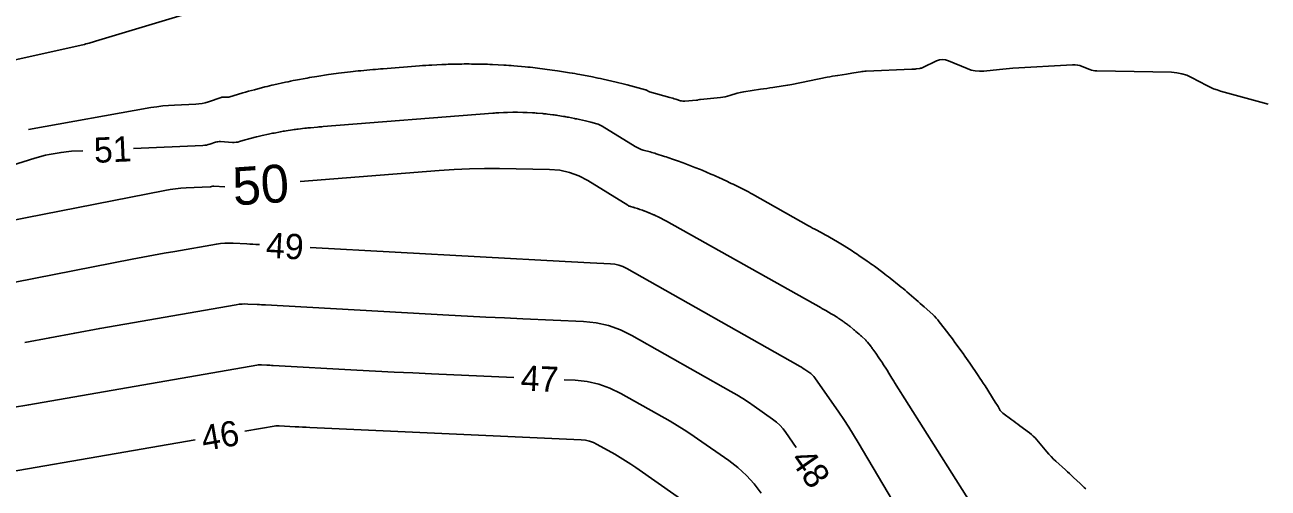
# Model space of a CAD drawing. Extents: x 2384780 to 2405861, y 547869 to 573706.
# Drawn here: x 2389798.2 to 2389896.5, y 552294.5 to 552331.2 of the extents above; entities that cross this region are included whole.
import ezdxf

# ---------------------------------------------------------------- set-up
doc = ezdxf.new("R2010")
doc.units = 0
doc.layers.add('Old_Level_60', color=7, linetype='Continuous')
doc.layers.add('Old_Level_61', color=7, linetype='Continuous')

msp = doc.modelspace()

# ---------------------------------------------------------------- linework, layer by layer
at = {"layer": 'Old_Level_60'}
for points in [[(2389788.7195, 552326.3875), (2389790.72825, 552326.88275), (2389792.092, 552327.21475), (2389793.45775, 552327.5385), (2389794.82525, 552327.854), (2389796.19475, 552328.1615), (2389802.73375, 552329.609), (2389802.86175, 552329.6385), (2389802.98925, 552329.6705), (2389803.116, 552329.705), (2389803.242, 552329.742), (2389803.653, 552329.8665), (2389803.741, 552329.893), (2389803.829, 552329.91975), (2389803.91725, 552329.94625), (2389804.00525, 552329.97275), (2389822.38525, 552335.50225)], [(2389798.453, 552322.90375), (2389808.1335, 552324.6305), (2389808.59675, 552324.70525), (2389809.06175, 552324.7645), (2389809.52825, 552324.8085), (2389809.99675, 552324.83725), (2389811.675, 552324.912), (2389811.929, 552324.932), (2389812.18, 552324.96975), (2389812.42775, 552325.02475), (2389812.67225, 552325.097), (2389813.688, 552325.4365), (2389813.74725, 552325.45325), (2389813.807, 552325.464), (2389813.8675, 552325.46875), (2389813.929, 552325.46775), (2389814.1305, 552325.455), (2389814.1735, 552325.454), (2389814.21625, 552325.457), (2389814.25825, 552325.4635), (2389814.3, 552325.474), (2389815.38925, 552325.79475), (2389815.623, 552325.8625), (2389815.85725, 552325.9285), (2389816.092, 552325.99225), (2389816.32725, 552326.05425), (2389817.1545, 552326.26825), (2389817.332, 552326.31325), (2389817.51, 552326.357), (2389817.688, 552326.399), (2389817.86675, 552326.4395), (2389818.7855, 552326.64375), (2389818.9825, 552326.68675), (2389819.18, 552326.72825), (2389819.37775, 552326.76775), (2389819.57575, 552326.806), (2389820.48225, 552326.9765), (2389820.6765, 552327.01225), (2389820.871, 552327.04625), (2389821.066, 552327.07875), (2389821.26125, 552327.1095), (2389822.18825, 552327.25175), (2389822.387, 552327.28125), (2389822.586, 552327.30925), (2389822.78525, 552327.33575), (2389822.9845, 552327.3605), (2389823.925, 552327.4735), (2389824.12675, 552327.497), (2389824.3285, 552327.51875), (2389824.5305, 552327.539), (2389824.7325, 552327.5575), (2389825.69175, 552327.64125), (2389825.8975, 552327.659), (2389826.103, 552327.6765), (2389826.30875, 552327.69325), (2389826.51425, 552327.70975), (2389829.38675, 552327.93725), (2389829.629, 552327.95575), (2389829.8715, 552327.97275), (2389830.114, 552327.988), (2389830.3565, 552328.00175), (2389831.149, 552328.04425), (2389831.31875, 552328.0525), (2389831.48875, 552328.0595), (2389831.65875, 552328.06475), (2389831.82875, 552328.06875), (2389832.73325, 552328.08525), (2389832.927, 552328.088), (2389833.121, 552328.089), (2389833.31475, 552328.08825), (2389833.5085, 552328.086), (2389834.39275, 552328.07125), (2389834.58225, 552328.06725), (2389834.77175, 552328.06175), (2389834.961, 552328.05425), (2389835.15025, 552328.04525), (2389836.058, 552327.998), (2389836.2525, 552327.987), (2389836.44675, 552327.97425), (2389836.641, 552327.96), (2389836.835, 552327.94375), (2389837.7565, 552327.863), (2389837.954, 552327.845), (2389838.15125, 552327.825), (2389838.34825, 552327.80325), (2389838.545, 552327.78), (2389839.4875, 552327.66375), (2389839.68925, 552327.638), (2389839.891, 552327.6105), (2389840.09225, 552327.58125), (2389840.2935, 552327.55025), (2389841.25875, 552327.39675), (2389841.4655, 552327.363), (2389841.67175, 552327.3275), (2389841.87775, 552327.29025), (2389842.0835, 552327.25125), (2389843.07675, 552327.0585), (2389843.28925, 552327.01625), (2389843.5015, 552326.972), (2389843.71325, 552326.92625), (2389843.92475, 552326.8785)], [(2389843.92475, 552326.8785), (2389844.94875, 552326.6425), (2389845.16775, 552326.591), (2389845.3865, 552326.53775), (2389845.60475, 552326.48275), (2389845.8225, 552326.42575), (2389847.2715, 552326.041), (2389847.304, 552326.031), (2389847.3355, 552326.01875), (2389847.366, 552326.00425), (2389847.39575, 552325.9875), (2389847.4905, 552325.92875), (2389847.51125, 552325.917), (2389847.5325, 552325.90675), (2389847.5545, 552325.898), (2389847.57725, 552325.89075), (2389849.18925, 552325.44225), (2389849.30775, 552325.4085), (2389849.426, 552325.374), (2389849.544, 552325.3385), (2389849.6615, 552325.302), (2389850.0455, 552325.18125), (2389850.128, 552325.1595), (2389850.21175, 552325.14575), (2389850.29625, 552325.14025), (2389850.38175, 552325.143), (2389851.3085, 552325.2155), (2389851.3405, 552325.21875), (2389851.37225, 552325.22375), (2389851.4035, 552325.23025), (2389851.43475, 552325.23825), (2389851.536, 552325.26675), (2389851.55775, 552325.2725), (2389851.57975, 552325.27725), (2389851.60175, 552325.281), (2389851.62425, 552325.28375), (2389853.20075, 552325.44425), (2389853.388, 552325.468), (2389853.57325, 552325.50025), (2389853.757, 552325.54125), (2389853.93875, 552325.59125), (2389854.53, 552325.7685), (2389854.65725, 552325.80425), (2389854.7855, 552325.8355), (2389854.91475, 552325.862), (2389855.045, 552325.88425), (2389856.369, 552326.0855), (2389856.616, 552326.12275), (2389856.863, 552326.16025), (2389857.11, 552326.19725), (2389857.35725, 552326.23425), (2389858.16425, 552326.355), (2389858.337, 552326.38175), (2389858.5095, 552326.41075), (2389858.6815, 552326.442), (2389858.85325, 552326.475), (2389861.65625, 552327.034), (2389861.86325, 552327.0745), (2389862.0705, 552327.113), (2389862.27825, 552327.1495), (2389862.48625, 552327.18425), (2389863.16625, 552327.295), (2389863.312, 552327.3185), (2389863.45775, 552327.342), (2389863.60375, 552327.36525), (2389863.7495, 552327.3885), (2389864.27675, 552327.472), (2389864.39, 552327.48825), (2389864.5035, 552327.50125), (2389864.61725, 552327.511), (2389864.73125, 552327.5175), (2389868.3535, 552327.67025), (2389868.44, 552327.67475), (2389868.52625, 552327.68125), (2389868.6125, 552327.6895), (2389868.6985, 552327.6995), (2389868.9795, 552327.73575), (2389869.039, 552327.74575), (2389869.097, 552327.7605), (2389869.15375, 552327.78), (2389869.209, 552327.80375), (2389870.29525, 552328.32675), (2389870.52875, 552328.412), (2389870.76325, 552328.44425), (2389870.99925, 552328.42325), (2389871.23625, 552328.349), (2389872.71625, 552327.72125), (2389873.03675, 552327.60825), (2389873.36325, 552327.53825), (2389873.69625, 552327.51125), (2389874.0355, 552327.5275), (2389875.2695, 552327.66325), (2389875.534, 552327.69075), (2389875.79875, 552327.7145), (2389876.064, 552327.73475), (2389876.32925, 552327.75175), (2389881.06425, 552328.02025), (2389881.26175, 552328.02075), (2389881.4555, 552328), (2389881.64575, 552327.95775), (2389881.8325, 552327.894)], [(2389881.8325, 552327.894), (2389882.437, 552327.651), (2389882.56775, 552327.60525), (2389882.701, 552327.5715), (2389882.83675, 552327.5505), (2389882.975, 552327.5415), (2389888.8875, 552327.428), (2389889.30275, 552327.39625), (2389889.70575, 552327.3175), (2389890.09675, 552327.1915), (2389890.4755, 552327.0185), (2389891.693, 552326.37625), (2389891.957, 552326.246), (2389892.2265, 552326.13025), (2389892.502, 552326.0295), (2389892.78325, 552325.94325), (2389896.54125, 552324.89975)], [(2389806.74775, 552321.395), (2389812.2445, 552321.64), (2389812.386, 552321.651), (2389812.52575, 552321.672), (2389812.66375, 552321.70275), (2389812.8, 552321.743), (2389813.24175, 552321.89075), (2389813.337, 552321.9175), (2389813.4335, 552321.935), (2389813.5315, 552321.94275), (2389813.6305, 552321.94125), (2389814.582, 552321.88025), (2389814.72475, 552321.8775), (2389814.86625, 552321.887), (2389815.00625, 552321.90875), (2389815.14475, 552321.94325), (2389815.59525, 552322.076), (2389815.692, 552322.104), (2389815.78875, 552322.13125), (2389815.886, 552322.15775), (2389815.98325, 552322.18325), (2389816.49575, 552322.316), (2389816.60575, 552322.34375), (2389816.716, 552322.37075), (2389816.8265, 552322.39675), (2389816.937, 552322.422), (2389817.43775, 552322.53325), (2389817.545, 552322.55675), (2389817.65275, 552322.57925), (2389817.7605, 552322.601), (2389817.86825, 552322.62175), (2389818.38125, 552322.71825), (2389818.491, 552322.73825), (2389818.60125, 552322.75775), (2389818.7115, 552322.776), (2389818.822, 552322.7935), (2389819.3405, 552322.873), (2389819.45175, 552322.8895), (2389819.563, 552322.90525), (2389819.6745, 552322.92), (2389819.786, 552322.93375), (2389820.314, 552322.99725), (2389820.42725, 552323.0105), (2389820.5405, 552323.02275), (2389820.65375, 552323.034), (2389820.76725, 552323.0445), (2389821.30525, 552323.0915), (2389821.4205, 552323.1015), (2389821.53575, 552323.111), (2389821.651, 552323.1205), (2389821.76625, 552323.12975), (2389835.19225, 552324.19325), (2389835.30625, 552324.20175), (2389835.42025, 552324.20975), (2389835.5345, 552324.217), (2389835.6485, 552324.2235), (2389836.02175, 552324.2435), (2389836.10175, 552324.2475), (2389836.18175, 552324.25075), (2389836.26175, 552324.25325), (2389836.34175, 552324.255), (2389836.7675, 552324.26275), (2389836.85875, 552324.264), (2389836.95, 552324.2645), (2389837.04125, 552324.26425), (2389837.1325, 552324.263), (2389837.54875, 552324.25625), (2389837.638, 552324.25425), (2389837.72725, 552324.25175), (2389837.81625, 552324.24825), (2389837.9055, 552324.244), (2389838.33275, 552324.22175), (2389838.42425, 552324.2165), (2389838.51575, 552324.2105), (2389838.607, 552324.20375), (2389838.6985, 552324.19625), (2389839.13225, 552324.15825), (2389839.22525, 552324.14975), (2389839.318, 552324.14025), (2389839.41075, 552324.13), (2389839.5035, 552324.119), (2389839.94725, 552324.0645), (2389840.04225, 552324.05225), (2389840.137, 552324.03925), (2389840.23175, 552324.0255), (2389840.3265, 552324.011), (2389840.781, 552323.93875), (2389840.87825, 552323.92275), (2389840.9755, 552323.90625), (2389841.0725, 552323.8885), (2389841.16925, 552323.87025), (2389841.63675, 552323.7795), (2389841.737, 552323.7595), (2389841.83675, 552323.73875), (2389841.9365, 552323.71725), (2389842.036, 552323.69475), (2389842.518, 552323.5835), (2389842.62125, 552323.5595), (2389842.72425, 552323.53425), (2389842.827, 552323.5085), (2389842.9295, 552323.4815)], [(2389842.9295, 552323.4815), (2389843.42875, 552323.349), (2389843.534, 552323.31675), (2389843.63625, 552323.27725), (2389843.73525, 552323.23025), (2389843.831, 552323.17575), (2389846.4485, 552321.5575), (2389846.6015, 552321.47025), (2389846.75925, 552321.39425), (2389846.922, 552321.32975), (2389847.08975, 552321.27675), (2389847.646, 552321.122), (2389847.765, 552321.08825), (2389847.88375, 552321.0535), (2389848.00225, 552321.018), (2389848.1205, 552320.98125), (2389848.76925, 552320.777), (2389848.908, 552320.7325), (2389849.0465, 552320.687), (2389849.1845, 552320.6405), (2389849.322, 552320.59275), (2389849.96525, 552320.3665), (2389850.103, 552320.31725), (2389850.24025, 552320.26725), (2389850.377, 552320.216), (2389850.5135, 552320.1635), (2389851.183, 552319.903), (2389851.32625, 552319.84675), (2389851.469, 552319.78925), (2389851.6115, 552319.73075), (2389851.75325, 552319.671), (2389852.443, 552319.37725), (2389852.5905, 552319.31375), (2389852.7375, 552319.249), (2389852.884, 552319.18325), (2389853.03, 552319.11625), (2389853.745, 552318.785), (2389853.898, 552318.7135), (2389854.05025, 552318.6405), (2389854.202, 552318.56675), (2389854.35325, 552318.4915), (2389855.09525, 552318.11925), (2389855.25375, 552318.0385), (2389855.41125, 552317.95575), (2389855.56775, 552317.8715), (2389855.72325, 552317.785), (2389860.16525, 552315.28525), (2389860.329, 552315.19375), (2389860.493, 552315.1035), (2389860.65775, 552315.01375), (2389860.823, 552314.92525), (2389861.3635, 552314.6375), (2389861.479, 552314.57525), (2389861.594, 552314.512), (2389861.70825, 552314.44775), (2389861.822, 552314.38225), (2389862.4565, 552314.01275), (2389862.592, 552313.93275), (2389862.72675, 552313.85175), (2389862.861, 552313.7695), (2389862.99425, 552313.686), (2389863.6255, 552313.286), (2389863.76025, 552313.19975), (2389863.89425, 552313.112), (2389864.0275, 552313.02325), (2389864.16, 552312.93325), (2389864.82, 552312.47975), (2389864.961, 552312.382), (2389865.10125, 552312.28275), (2389865.24025, 552312.18225), (2389865.3785, 552312.0805), (2389866.0615, 552311.573), (2389866.2075, 552311.46375), (2389866.35225, 552311.353), (2389866.49625, 552311.241), (2389866.639, 552311.12775), (2389867.35175, 552310.558), (2389867.50375, 552310.43525), (2389867.655, 552310.31125), (2389867.805, 552310.186), (2389867.95375, 552310.05925), (2389868.69925, 552309.4195), (2389868.8585, 552309.282), (2389869.0165, 552309.143), (2389869.1735, 552309.0025), (2389869.32925, 552308.861), (2389869.997, 552308.24925), (2389870.13725, 552308.11525), (2389870.271, 552307.97575), (2389870.399, 552307.8305), (2389870.5205, 552307.67975), (2389871.194, 552306.8075), (2389871.3375, 552306.62), (2389871.4795, 552306.43125), (2389871.62025, 552306.24175), (2389871.75925, 552306.051), (2389872.40075, 552305.16375), (2389872.5375, 552304.973), (2389872.67275, 552304.7815), (2389872.80675, 552304.58875), (2389872.93925, 552304.39525)], [(2389787.4015, 552317.024), (2389798.94025, 552320.63875), (2389799.2215, 552320.722), (2389799.50475, 552320.796), (2389799.79025, 552320.86125), (2389800.078, 552320.91725), (2389801.02175, 552321.0855), (2389801.22425, 552321.11825), (2389801.42775, 552321.14425), (2389801.63175, 552321.1635), (2389801.8365, 552321.176), (2389802.75175, 552321.21675)], [(2389786.4935, 552308.68425), (2389806.6455, 552312.63175), (2389807.48875, 552312.79475), (2389808.33275, 552312.953), (2389809.17775, 552313.1065), (2389810.0235, 552313.25575), (2389813.3155, 552313.827), (2389813.6445, 552313.87475), (2389813.97475, 552313.9035), (2389814.306, 552313.91325), (2389814.63825, 552313.90425), (2389815.72575, 552313.84425), (2389815.95875, 552313.8315), (2389816.19175, 552313.8185), (2389816.42475, 552313.80575), (2389816.65775, 552313.79275), (2389816.72725, 552313.789)], [(2389820.72125, 552313.5685), (2389840.9175, 552312.4535), (2389841.41, 552312.427), (2389841.9025, 552312.4015), (2389842.39525, 552312.3775), (2389842.888, 552312.35475), (2389844.49775, 552312.282), (2389844.837, 552312.24725), (2389845.16525, 552312.17375), (2389845.4825, 552312.0615), (2389845.7885, 552311.911), (2389859.31575, 552304.25775), (2389859.46225, 552304.1725), (2389859.6065, 552304.08375), (2389859.7485, 552303.9915), (2389859.8885, 552303.89575), (2389860.3415, 552303.577), (2389860.435, 552303.50525), (2389860.521, 552303.426), (2389860.59975, 552303.33925), (2389860.67125, 552303.2455), (2389862.56, 552300.52575), (2389862.95925, 552299.9395), (2389863.348, 552299.34625), (2389863.72575, 552298.746), (2389864.09275, 552298.139), (2389871.15225, 552286.21825)], [(2389798.14025, 552306.04125), (2389800.11925, 552306.4235), (2389802.10025, 552306.79475), (2389804.08325, 552307.1555), (2389806.068, 552307.5055), (2389814.8815, 552309.03525), (2389815.10875, 552309.068), (2389815.337, 552309.088), (2389815.566, 552309.09475), (2389815.79575, 552309.0885), (2389816.5475, 552309.047), (2389816.7085, 552309.03825), (2389816.8695, 552309.02925), (2389817.03075, 552309.0205), (2389817.19175, 552309.0115), (2389831.71375, 552308.20975), (2389833.17825, 552308.13075), (2389834.64275, 552308.0555), (2389836.10775, 552307.98375), (2389837.57275, 552307.91575), (2389842.35875, 552307.7), (2389843.368, 552307.59625), (2389844.344, 552307.37775), (2389845.287, 552307.0445), (2389846.19725, 552306.59625), (2389854.026, 552302.16725), (2389854.49725, 552301.893), (2389854.96125, 552301.6075), (2389855.418, 552301.31075), (2389855.86775, 552301.0025), (2389857.325, 552299.97775), (2389857.6255, 552299.7465), (2389857.9025, 552299.4915), (2389858.15575, 552299.21325), (2389858.38525, 552298.9115), (2389859.19825, 552297.741)], [(2389836.843, 552303.27025), (2389830.3345, 552303.56375), (2389828.8585, 552303.63225), (2389827.38275, 552303.7045), (2389825.90725, 552303.78025), (2389824.432, 552303.85975), (2389817.802, 552304.226), (2389817.67475, 552304.233), (2389817.5475, 552304.24), (2389817.42, 552304.247), (2389817.29275, 552304.254), (2389816.87675, 552304.277), (2389816.78775, 552304.2795), (2389816.699, 552304.27675), (2389816.61075, 552304.269), (2389816.5225, 552304.25625), (2389798.464, 552301.122), (2389797.16325, 552300.89275)], [(2389872.93925, 552304.39525), (2389873.5895, 552303.4365), (2389873.728, 552303.23075), (2389873.86525, 552303.02375), (2389874.00075, 552302.81575), (2389874.13475, 552302.60675), (2389874.949, 552301.32625), (2389875.005, 552301.23725), (2389875.0605, 552301.148), (2389875.1155, 552301.05825), (2389875.1695, 552300.968), (2389875.3455, 552300.6725), (2389875.38575, 552300.61175), (2389875.4315, 552300.55575), (2389875.48275, 552300.50475), (2389875.53925, 552300.4585), (2389876.26925, 552299.9195), (2389876.4255, 552299.804), (2389876.58175, 552299.68825), (2389876.73775, 552299.57225), (2389876.89375, 552299.45625), (2389877.65025, 552298.89175), (2389877.8085, 552298.7665), (2389877.9585, 552298.633), (2389878.10075, 552298.49075), (2389878.235, 552298.34025), (2389879.02625, 552297.39975), (2389879.19875, 552297.201), (2389879.3775, 552297.00825), (2389879.56225, 552296.82125), (2389879.75325, 552296.64025), (2389880.499, 552295.9555), (2389880.65875, 552295.80875), (2389880.818, 552295.66125), (2389880.977, 552295.51375), (2389881.13575, 552295.36575), (2389881.659, 552294.876), (2389881.771, 552294.771), (2389881.88275, 552294.6655), (2389881.994, 552294.55975), (2389882.105, 552294.4535)], [(2389856.4145, 552294.12325), (2389855.8605, 552294.85175), (2389855.2495, 552295.52325), (2389854.5815, 552296.13825), (2389853.8565, 552296.6965), (2389851.39475, 552298.4275), (2389850.86325, 552298.79175), (2389850.323, 552299.1425), (2389849.7745, 552299.48025), (2389849.21725, 552299.80425), (2389845.308, 552302.016), (2389844.45475, 552302.43625), (2389843.57075, 552302.74875), (2389842.6555, 552302.9535), (2389841.7095, 552303.05075), (2389840.839, 552303.09)], [(2389851.26625, 552292.7975), (2389846.50775, 552296.14375), (2389846.10275, 552296.421), (2389845.6915, 552296.68825), (2389845.27375, 552296.94525), (2389844.8495, 552297.192), (2389843.4535, 552297.982), (2389843.14875, 552298.132), (2389842.833, 552298.2435), (2389842.50625, 552298.31675), (2389842.1685, 552298.3515), (2389820.69175, 552299.32025), (2389820.40725, 552299.3335), (2389820.1225, 552299.34725), (2389819.83775, 552299.362), (2389819.55325, 552299.37725), (2389818.27425, 552299.448), (2389818.24975, 552299.44925), (2389818.22525, 552299.45075), (2389818.20075, 552299.452), (2389818.176, 552299.45325), (2389818.096, 552299.45775), (2389818.07875, 552299.45825), (2389818.0615, 552299.45775), (2389818.0445, 552299.45625), (2389818.0275, 552299.45375), (2389815.563, 552299.026)], [(2389811.62175, 552298.342), (2389789.94775, 552294.5805)]]:
    msp.add_lwpolyline(points, dxfattribs=at)
at = {"layer": 'Old_Level_61'}
for points in [[(2389819.93725, 552318.781), (2389830.944, 552319.65275), (2389832.138, 552319.73325), (2389833.333, 552319.78525), (2389834.52875, 552319.809), (2389835.7255, 552319.8045), (2389839.67075, 552319.743), (2389840.47625, 552319.67775), (2389841.251, 552319.50775), (2389841.99525, 552319.23325), (2389842.70875, 552318.854), (2389845.868, 552316.90075), (2389845.9185, 552316.872), (2389845.9705, 552316.847), (2389846.02425, 552316.82575), (2389846.07975, 552316.80825), (2389846.2635, 552316.757), (2389846.30275, 552316.746), (2389846.342, 552316.7345), (2389846.38125, 552316.72275), (2389846.42025, 552316.7105), (2389846.6345, 552316.643), (2389846.68025, 552316.6285), (2389846.726, 552316.61325), (2389846.77175, 552316.598), (2389846.817, 552316.58225), (2389847.0295, 552316.5075), (2389847.075, 552316.49125), (2389847.12025, 552316.47475), (2389847.1655, 552316.45775), (2389847.2105, 552316.4405), (2389847.43175, 552316.3545), (2389847.479, 552316.33575), (2389847.52625, 552316.31675), (2389847.57325, 552316.2975), (2389847.62025, 552316.27775), (2389847.848, 552316.18075), (2389847.89675, 552316.15975), (2389847.94525, 552316.13825), (2389847.99375, 552316.11675), (2389848.042, 552316.0945), (2389848.278, 552315.985), (2389848.3285, 552315.9615), (2389848.379, 552315.93725), (2389848.429, 552315.913), (2389848.479, 552315.888), (2389848.724, 552315.765), (2389848.7765, 552315.7385), (2389848.8285, 552315.71125), (2389848.88025, 552315.68325), (2389848.9315, 552315.65475), (2389861.158, 552308.77425), (2389861.216, 552308.74175), (2389861.27425, 552308.70975), (2389861.3325, 552308.678), (2389861.391, 552308.64675), (2389861.5825, 552308.54475), (2389861.6235, 552308.52275), (2389861.66425, 552308.50025), (2389861.70475, 552308.4775), (2389861.745, 552308.45425), (2389861.96975, 552308.32325), (2389862.01775, 552308.295), (2389862.0655, 552308.26625), (2389862.113, 552308.23725), (2389862.16025, 552308.2075), (2389862.384, 552308.06575), (2389862.43175, 552308.03525), (2389862.47925, 552308.00425), (2389862.5265, 552307.97275), (2389862.5735, 552307.94075), (2389862.80725, 552307.78025), (2389862.85725, 552307.7455), (2389862.90675, 552307.71025), (2389862.95625, 552307.67475), (2389863.00525, 552307.63875), (2389863.24725, 552307.459), (2389863.29875, 552307.42025), (2389863.35025, 552307.381), (2389863.40125, 552307.34125), (2389863.45175, 552307.30125), (2389863.70425, 552307.09925), (2389863.75825, 552307.05575), (2389863.81175, 552307.01175), (2389863.86475, 552306.9675), (2389863.9175, 552306.9225), (2389864.18175, 552306.696), (2389864.23825, 552306.647), (2389864.29425, 552306.59775), (2389864.34975, 552306.54825), (2389864.405, 552306.498), (2389864.6415, 552306.28125), (2389864.69125, 552306.23375), (2389864.73875, 552306.18425), (2389864.784, 552306.13275), (2389864.827, 552306.0795), (2389865.06575, 552305.77025), (2389865.1165, 552305.704), (2389865.16675, 552305.637), (2389865.21675, 552305.57), (2389865.266, 552305.50225)], [(2389787.1615, 552313.75525), (2389809.2365, 552318.083), (2389809.65125, 552318.15625), (2389810.06775, 552318.214), (2389810.48625, 552318.25625), (2389810.9065, 552318.28275), (2389812.81375, 552318.36775), (2389812.84275, 552318.37), (2389812.8715, 552318.3745), (2389812.89975, 552318.38075), (2389812.9275, 552318.389), (2389813.018, 552318.41925), (2389813.0375, 552318.42475), (2389813.0575, 552318.42825), (2389813.0775, 552318.42975), (2389813.09775, 552318.4295), (2389813.97675, 552318.37325)], [(2389865.266, 552305.50225), (2389865.49325, 552305.188), (2389865.54175, 552305.1205), (2389865.58975, 552305.0525), (2389865.637, 552304.98425), (2389865.684, 552304.91575), (2389865.9145, 552304.576), (2389865.9635, 552304.503), (2389866.012, 552304.42975), (2389866.06025, 552304.356), (2389866.1075, 552304.282), (2389866.3375, 552303.92025), (2389866.3865, 552303.84275), (2389866.435, 552303.76475), (2389866.48275, 552303.68625), (2389866.53, 552303.6075), (2389866.76125, 552303.2195), (2389866.811, 552303.1365), (2389866.86125, 552303.054), (2389866.91225, 552302.97175), (2389866.9635, 552302.88975), (2389873.77, 552292.12525)]]:
    msp.add_lwpolyline(points, dxfattribs=at)

# ---------------------------------------------------------------- texts
at = {"layer": 'Old_Level_60'}
for s, rotation, p in [('51', 2.5523972, (2389803.66175, 552320.25625)), ('49', 356.8399306, (2389817.19125, 552312.762)), ('47', 357.4172222, (2389837.3645, 552302.24575)), ('46', 9.8458889, (2389812.305, 552297.44575)), ('48', 304.7782861, (2389858.65975, 552296.76275))]:
    msp.add_text(s, height=2, rotation=rotation, dxfattribs=at).set_placement(p)
at = {"layer": 'Old_Level_61'}
msp.add_text('50', height=3, rotation=3.9131333, dxfattribs=at).set_placement((2389814.6925, 552316.88625))

doc.saveas('drawing.dxf')
